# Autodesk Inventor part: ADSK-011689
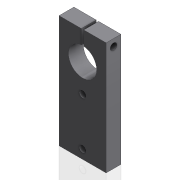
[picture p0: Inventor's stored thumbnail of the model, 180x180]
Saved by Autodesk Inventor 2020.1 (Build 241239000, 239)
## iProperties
Created: 2000-02
Part Number: ADSK-011689
Material: Pearson HRS
Document SubType Name: Modeling
Designer: glanglot
Density: 7.83 g/cm^3
Appearance: Métal - Acier
Mass: 1280.39 g
Surface Area: 307.134 cm^2
Volume: 163.523 cm^3
Control State: 0
Checked Out: False
Master: False
Shininess: 0.0
Length Units: 11269
Angle Units: 11279
Time Units: 11290
Mass Units: 11283
Length Display Precision: 3
Angle Display Precision: 2
Compacted: True
Cutlength: 23.25
Material Desc: Material Description goes here
Material_Number: Pearson
Dimensions: 63,5x152x20 mm
Mass: 1,28 kg
Density: 0.0
Volumn: 0.0
Area: 0.0
PropertySet Name: Model Information
Author: glanglot
Revision Number: -
Title: ADSK-011689
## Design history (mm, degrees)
node "Solide1"
  node "Extrusion1" dims "d7" = 20, "d8" = 0
  node "Hole1" dims "d9" = 9, "d10" = 9.525, "d11" = 6.35, "d12" = 60 deg, "d13" = 19.05, "d14" = 118 deg, "d32" = 6
  node "Extrusion2" dims "d17" = 19.05, "d18" = 0
  node "Hole2" dims "d20" = 6.647, "d21" = 9.525, "d22" = 6.35, "d23" = 60 deg, "d24" = 19.05, "d25" = 118 deg, "d33" = 16
  node "Hole3" dims "d26" = 9, "d27" = 9.525, "d28" = 6.35, "d29" = 60 deg, "d30" = 19.05, "d31" = 118 deg, "d34" = 6
sketch "Sketch1"
  geometry: L1 (-31.75, 38)-(31.75, 38); L2 (31.75, 38)-(31.75, -114); L3 (31.75, -114)-(-31.75, -114); L4 (-31.75, -114)-(-31.75, 38); L5 (0, 38)-(0, -114); C1 r 19.05 at (0, 0); 3 further points
  constraints: 10 end point, 3 midpoint, 2 parallel, 2 point on line, 1 centre point, 1 coincident, 1 horizontal, 1 perpendicular
  dimensions: "d0" = 38 distance from line of C1.centre L1; "d1" = 152 distance between parallel lines of L3 L1; "d2" = 63.5 distance between parallel lines of L4 L2; "d3" = 38.1 diameter of C1; "d5" = 76 distance from line of point (0, -38) L1; "d6" = 140 distance from line of point (0, -102) L1
sketch "Sketch3"
  geometry: L1 (0, 152)-(20, 152) reference; L2 (0, 0)-(20, 0) reference; L3 (10, 152)-(10, 0); 1 further point
  constraints: 2 end point, 2 midpoint, 1 point on line
  dimensions: "d19" = 9.5 distance from line of point (10, 142.5) L1
node "Corps solides"
node "Corps surfaciques"
sketch "Sketch2"
  geometry: L1 (-31.75, 38)-(31.75, 38) reference; L2 (0, 0)-(0, 38); L3 (1.587, 38)-(1.587, 18.984); L4 (-1.587, 38)-(-1.587, 18.984); A1 r 19.05 centre (0, 0) between (1.587, 18.984) and (-1.587, 18.984) reference
  constraints: 6 end point, 2 perpendicular, 2 point on circle, 2 point on line, 1 midpoint, 1 parallel
  dimensions: "d15" = 1.5875 distance between parallel lines of L2 L4; "d16" = 1.5875 distance between parallel lines of L3 L2
sketch "Sketch4"
  geometry: C1 r 3.324 at (-10, 142.5) reference; 1 further point
  constraints: 1 coincident
